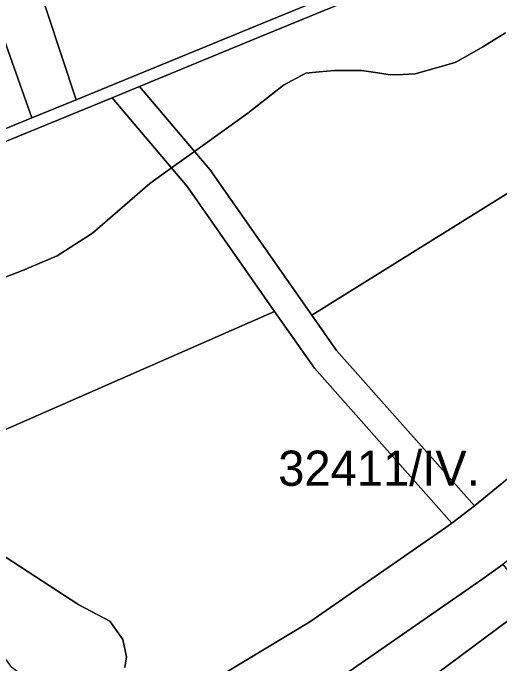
# Model space of a CAD drawing. Extents: x -522079 to -518792, y -1142400 to -1139961.
# Drawn here: x -520209.8 to -520002.4, y -1140798.1 to -1140520.9 of the extents above; entities that cross this region are included whole.
import ezdxf

# ---------------------------------------------------------------- set-up
doc = ezdxf.new("R2010")
doc.units = 0
for name, color, linetype in [('Hranice parcel', 7, 'Continuous'), ('Parcelní čísla', 7, 'Continuous'), ('Poz předměty', 7, 'Continuous'), ('Značky bodu BP', 7, 'Continuous')]:
    doc.layers.add(name, color=color, linetype=linetype)

msp = doc.modelspace()

# ---------------------------------------------------------------- linework, layer by layer
at = {"layer": 'Hranice parcel'}
msp.add_lwpolyline([(-519947.24, -1140466.47), (-520104.66, -1140531.14), (-520155.91, -1140552.2), (-520167.57, -1140556.99), (-520262.2, -1140595.87), (-520287.56, -1140604.5), (-520318.61, -1140618.22), (-520330.21, -1140624.54), (-520334.77, -1140627.95), (-520334.5, -1140634.63), (-520342.44, -1140624.55), (-520317.54, -1140611.38), (-520303.27, -1140605.8), (-520289.45, -1140599.87), (-520277.29, -1140595.78), (-520263.96, -1140591.19), (-520201.76, -1140565.63), (-520182.86, -1140557.87), (-520106.55, -1140526.52), (-520084.71, -1140517.54), (-520041.44, -1140499.76), (-520031.39, -1140495.83), (-519949.02, -1140461.79)], dxfattribs=at)
msp.add_lwpolyline([(-520072.01, -1140664.71), (-520013.2, -1140730.8), (-520022.9, -1140738.15), (-520081.44, -1140672.17), (-520098.36, -1140648.01), (-520135.55, -1140594.91), (-520167.57, -1140556.99), (-520155.91, -1140552.2), (-520126.03, -1140587.59), (-520082.56, -1140649.64)], close=True, dxfattribs=at)
at = {"layer": 'Parcelní čísla'}
for points in [[(-520238.71, -1140389.58), (-520229.31, -1140381.82), (-520145.65, -1140338.22), (-520084.71, -1140517.54), (-520106.55, -1140526.52), (-520182.86, -1140557.87)], [(-520182.86, -1140557.87), (-520201.76, -1140565.63), (-520257.35, -1140408.66), (-520252.32, -1140400.85), (-520238.71, -1140389.58)], [(-520201.76, -1140565.63), (-520263.96, -1140591.19), (-520277.29, -1140595.78), (-520289.45, -1140599.87), (-520311.64, -1140535.23), (-520265.09, -1140420.72), (-520257.35, -1140408.66)], [(-519886.24, -1140527.38), (-520082.56, -1140649.64), (-520126.03, -1140587.59), (-520155.91, -1140552.2), (-520104.66, -1140531.14), (-519947.24, -1140466.47), (-519916.36, -1140457.2), (-519904.17, -1140458.14), (-519893.54, -1140491.71)], [(-519911.88, -1140647.84), (-520013.2, -1140730.8), (-520072.01, -1140664.71), (-520082.56, -1140649.64), (-519886.24, -1140527.38), (-519882.2, -1140547.1), (-519878.23, -1140567.62), (-519875.11, -1140585.42), (-519873.69, -1140593.69), (-519873.07, -1140596.47), (-519870.83, -1140606.54)], [(-520334.77, -1140627.95), (-520330.21, -1140624.54), (-520318.61, -1140618.22), (-520287.56, -1140604.5), (-520262.2, -1140595.87), (-520167.57, -1140556.99), (-520135.55, -1140594.91), (-520098.36, -1140648.01), (-520267.51, -1140722.14), (-520287.89, -1140694.59), (-520300.9, -1140678.05), (-520307.57, -1140669.43), (-520324.2, -1140648.06), (-520334.5, -1140634.63)], [(-520022.9, -1140738.15), (-520025.44, -1140739.97), (-520083.41, -1140780.15), (-520149.6, -1140820.02), (-520163.23, -1140814.61), (-520173.51, -1140811.18), (-520191.48, -1140809.25), (-520202.97, -1140805.12), (-520210.31, -1140799.64), (-520216.26, -1140791.5), (-520249.86, -1140745.99), (-520267.51, -1140722.14), (-520098.36, -1140648.01), (-520081.44, -1140672.17)], [(-520001.24, -1140755.77), (-519987.93, -1140771.54), (-520091.34, -1140848.28), (-520106.23, -1140841.79), (-520119.77, -1140834.99), (-520068.52, -1140802.68), (-520010.06, -1140762.16)], [(-520091.34, -1140848.28), (-519987.93, -1140771.54), (-519977.56, -1140783.82), (-519944.96, -1140804.75), (-519934.39, -1140809.6), (-520018.57, -1140878.52), (-520022.3, -1140876.95), (-520034.41, -1140872.06), (-520067.09, -1140858.86)]]:
    msp.add_lwpolyline(points, close=True, dxfattribs=at)
at = {"layer": 'Poz předměty'}
msp.add_lwpolyline([(-519862.3, -1140636.3), (-519893.23, -1140667.47), (-519991.87, -1140748.27), (-520001.24, -1140755.77), (-520010.06, -1140762.16), (-520068.52, -1140802.68), (-520119.77, -1140834.99), (-520149.6, -1140820.02), (-520083.41, -1140780.15), (-520025.44, -1140739.97), (-520022.9, -1140738.15), (-520013.2, -1140730.8), (-519911.88, -1140647.84), (-519870.83, -1140606.54), (-519868.76, -1140615.85)], close=True, dxfattribs=at)
at = {"layer": 'Značky bodu BP'}
for points in [[(-520224.27, -1140637.65), (-520205.8, -1140630.61), (-520191.03, -1140624.31), (-520175.88, -1140614.68), (-520151.5, -1140593.55), (-520142.29, -1140586.93), (-520132.52, -1140579.9), (-520109.76, -1140563.54), (-520094.62, -1140551.68), (-520085.02, -1140546.5), (-520079.42, -1140545.99), (-520072.83, -1140545.38), (-520061.38, -1140545.38), (-520055.47, -1140546.28), (-520049.19, -1140547.24), (-520043.83, -1140547.05), (-520038.47, -1140546.86), (-520021.48, -1140542.04), (-520016.4, -1140539.17), (-520009.66, -1140535.38), (-520000, -1140529.44)], [(-520000, -1140529.44), (-520009.66, -1140535.38), (-520016.4, -1140539.17), (-520021.48, -1140542.04), (-520038.47, -1140546.86), (-520043.83, -1140547.05), (-520049.19, -1140547.24), (-520055.47, -1140546.28), (-520061.38, -1140545.38), (-520072.83, -1140545.38), (-520079.42, -1140545.99), (-520085.02, -1140546.5), (-520094.62, -1140551.68), (-520109.76, -1140563.54), (-520132.52, -1140579.9), (-520142.29, -1140586.93), (-520151.5, -1140593.55), (-520175.88, -1140614.68), (-520191.03, -1140624.31), (-520205.8, -1140630.61), (-520224.27, -1140637.65)], [(-520162.22, -1140799.58), (-520161.48, -1140795.13), (-520162.96, -1140787.73), (-520168.5, -1140779.94), (-520181.79, -1140772.9), (-520216.15, -1140750.67)], [(-520216.15, -1140750.67), (-520181.79, -1140772.9), (-520168.5, -1140779.94), (-520162.96, -1140787.73), (-520161.48, -1140795.13), (-520162.22, -1140799.58)]]:
    msp.add_lwpolyline(points, dxfattribs=at)

# ---------------------------------------------------------------- texts
msp.add_text('32411/IV.', height=15, dxfattribs=at).set_placement((-520096.84, -1140722.28))

doc.saveas('drawing.dxf')
